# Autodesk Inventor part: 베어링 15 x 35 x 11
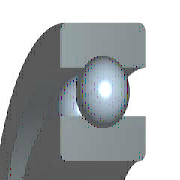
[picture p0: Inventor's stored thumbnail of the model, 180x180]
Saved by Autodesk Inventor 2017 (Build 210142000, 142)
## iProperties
Created: 2012-02
Part Number: 베어링 15 x 35 x 11
Material: 강철, 연강
Description: 깊은 그루브 볼 베어링
Document SubType Name: Modeling
Standard: KS B 2023
Designer: mduedu
Standards Organization: KS
Language: ko-KR
Size Designation: 6202 - 15 x 35 x 11
Categories: <MemberInstance><Categories><Category DisplayName="샤프트 부품" InternalName="7f7aeb1f-a693-4053-b835-cee3144e0d98" Mnemonic="SHFT"><Category DisplayName="베어링" Inter
Density: 1 g/cm^3
Appearance: 노란색
IsCustomPart: 1
Author: mduedu
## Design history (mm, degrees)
sketch "스케치" dims "d0" = 5.2 (= -0.26 x WD + 0.26 x BD)
  geometry: L1 (2.9, 12.5)-(8.1, 12.5); L2 (5.5, 12.5)-(5.5, 9.9); L3 (5.5, 12.5)-(5.5, 15.1); L4 (3.568, 10.76)-(0, 10.76); L5 (0, 7.5)-(11, 7.5); L6 (3.568, 14.24)-(0, 14.24); L7 (0, 17.5)-(11, 17.5); L8 (11, 7.5)-(11, 10.76); L9 (7.432, 10.76)-(11, 10.76); L10 (7.432, 14.24)-(11, 14.24); L11 (11, 17.5)-(11, 14.24); L12 (-1.4, 0)-(8.4, 0) reference; L13 (0, -0.3)-(0, 5.3) reference
  constraints: 22 end point, 4 point on line, 2 collinear, 2 perpendicular, 2 symmetric about line, 1 midpoint, 1 parallel, 14 other
  dimensions: "d9" = 15 diameter of L5 L12 (= WD); "d11" = 35 diameter of L7 L12 (= BD); "d12" = 11 distance between parallel lines of L8 L13 (= KB); "d13" = 21.52 diameter of L9 L12 (= 0.326 x BD + 0.674 x WD)
revolve "본체" stored, may be unused: angle "d6" = 90 deg
revolve "볼" stored, may be unused: angle "d7" = 90 deg
pattern_circular "IDS_ARRAYBALL[SIMPL:T]" dims angle "d3" = 360 deg
body "Solid1"
fillet "모깎기1" dims "d1" = 0.6 (= KRS)
other parameters: "WD" = 15 [user parameter; used in 5 equation terms], "BD" = 35 [user parameter; used in 5 equation terms], "KB" = 11 [user parameter; used in 1 equation term], "KRS" = 0.6 [user parameter; used in 1 equation term], "d4" = 0, "d5" = 0, "d8" = 0, "d14" = 0, "d15" = 0, "BBA" = 0 [user parameter], "BC0" = 3750000 [user parameter], "BC" = 7800000 [user parameter], "BR" = 17.5 (= 0.5 x BD) [user parameter], "WR" = 7.5 (= 0.5 x WD) [user parameter]
